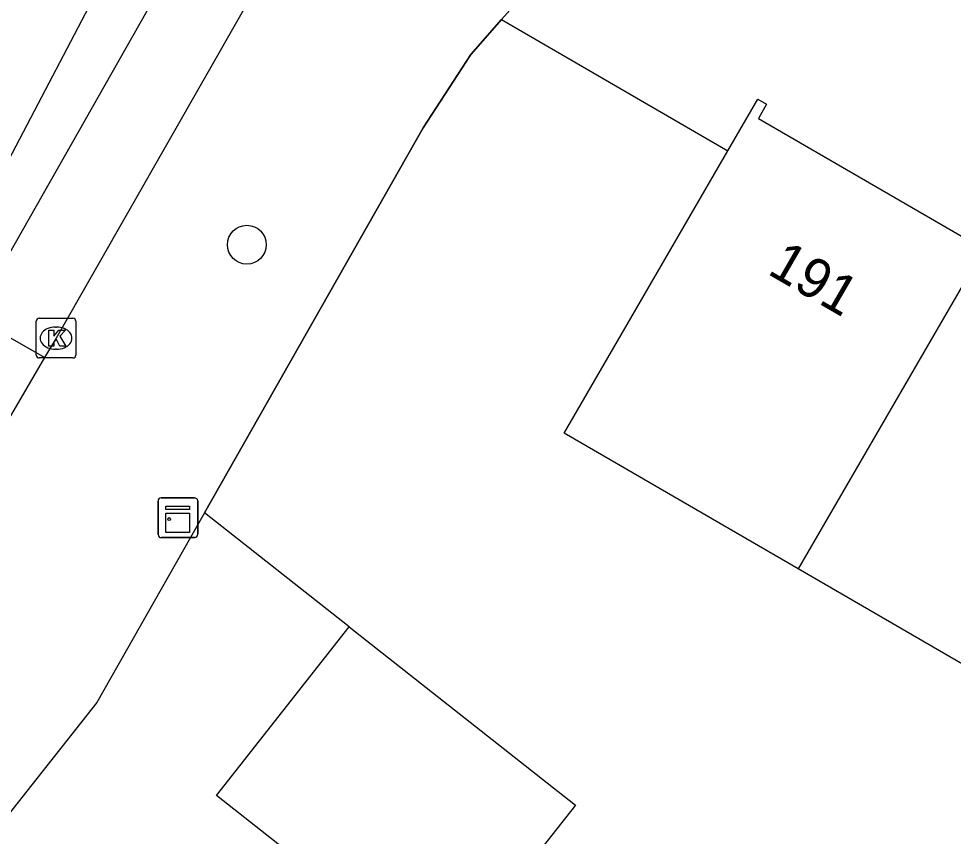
# Model space of a CAD drawing. Extents: x 160158 to 160921, y 381517 to 382041.
# Drawn here: x 160643.01 to 160666.58, y 381843.43 to 381864.05 of the extents above; entities that cross this region are included whole.
import ezdxf

# ---------------------------------------------------------------- set-up
doc = ezdxf.new("R2010")
doc.units = 0
for name, color, linetype in [('IMGEO_Boom', 7, 'Continuous'), ('IMGEO_Fietspad_open', 7, 'Continuous'), ('IMGEO_Kast', 7, 'Continuous'), ('IMGEO_Kolk', 7, 'Continuous'), ('IMGEO_Muur', 7, 'Continuous'), ('IMGEO_Pand', 7, 'Continuous'), ('IMGEO_Pand_nummerreeks', 7, 'Continuous'), ('IMGEO_Rijbaan_lokaal_gesloten', 7, 'Continuous'), ('IMGEO_Rijbaan_lokaal_open', 7, 'Continuous'), ('IMGEO_Voetpad_open', 7, 'Continuous')]:
    doc.layers.add(name, color=color, linetype=linetype)

msp = doc.modelspace()

# ---------------------------------------------------------------- linework, layer by layer
at = {"layer": 'IMGEO_Boom'}
msp.add_circle((160648.766, 381858.348), 0.489, dxfattribs=at)
at = {"layer": 'IMGEO_Fietspad_open'}
for points in [[(160653.156, 381872.105), (160648.639, 381864.194), (160643.955, 381855.993), (160643.662, 381855.505)], [(160641.866, 381856.528), (160648.195, 381867.674)]]:
    msp.add_lwpolyline(points, dxfattribs=at)
at = {"layer": 'IMGEO_Kast'}
for p, q in [((160646.528, 381851.04), (160646.528, 381851.881)), ((160646.528, 381851.881), (160646.528, 381851.04)), ((160646.603, 381851.965), (160647.444, 381851.965)), ((160647.444, 381851.965), (160646.603, 381851.965)), ((160647.528, 381851.89), (160647.528, 381851.049)), ((160647.528, 381851.049), (160647.528, 381851.89)), ((160647.453, 381850.965), (160646.612, 381850.965)), ((160646.612, 381850.965), (160647.453, 381850.965))]:
    msp.add_line(p, q, dxfattribs=at)
for points in [[(160646.723, 381851.755), (160647.323, 381851.755), (160647.323, 381851.67), (160646.723, 381851.67), (160646.723, 381851.755)], [(160646.723, 381851.58), (160647.323, 381851.58), (160647.323, 381851.091), (160646.723, 381851.091), (160646.723, 381851.58)]]:
    msp.add_lwpolyline(points, dxfattribs=at)
msp.add_circle((160646.807, 381851.429), 0.0377, dxfattribs=at)
for centre, start, end in [((160646.606, 381851.887), 92.4484, 184.2845), ((160646.606, 381851.887), 92.4484, 184.2845), ((160647.45, 381851.887), 2.4484, 94.2845), ((160647.45, 381851.887), 2.4484, 94.2845), ((160646.606, 381851.043), 182.4484, 274.2845), ((160646.606, 381851.043), 182.4484, 274.2845), ((160647.45, 381851.043), 272.4484, 4.2845), ((160647.45, 381851.043), 272.4484, 4.2845)]:
    msp.add_arc(centre, 0.0779, start, end, dxfattribs=at)
at = {"layer": 'IMGEO_Kolk'}
for p, q in [((160643.454, 381855.567), (160643.454, 381856.419)), ((160643.529, 381856.493), (160644.381, 381856.493)), ((160644.455, 381856.419), (160644.455, 381855.567)), ((160643.942, 381856.273), (160643.967, 381856.273)), ((160643.965, 381855.713), (160643.94, 381855.713)), ((160644.381, 381855.493), (160643.529, 381855.493))]:
    msp.add_line(p, q, dxfattribs=at)
for points in [[(160643.454, 381855.567), (160643.454, 381856.419)], [(160643.529, 381856.493), (160644.381, 381856.493)], [(160644.455, 381856.419), (160644.455, 381855.567)], [(160643.775, 381856.193), (160643.898, 381856.193), (160643.898, 381856.042), (160644.028, 381856.193), (160644.192, 381856.193), (160644.046, 381856.042), (160644.199, 381855.793), (160644.047, 381855.793), (160643.962, 381855.957), (160643.898, 381855.89), (160643.898, 381855.793), (160643.775, 381855.793), (160643.775, 381856.193)], [(160644.381, 381855.493), (160643.529, 381855.493)]]:
    msp.add_lwpolyline(points, dxfattribs=at)
for centre, start, end in [((160643.531, 381856.417), 91.552, 178.448), ((160643.531, 381856.417), 91.552, 178.448), ((160644.379, 381856.417), 1.552, 88.448), ((160644.379, 381856.417), 1.552, 88.448), ((160643.531, 381855.569), 181.552, 268.448), ((160643.531, 381855.569), 181.552, 268.448), ((160644.379, 381855.569), 271.552, 358.448), ((160644.379, 381855.569), 271.552, 358.448)]:
    msp.add_arc(centre, 0.0765, start, end, dxfattribs=at)
for centre, major_axis, ratio, start_param, end_param in [((160643.941, 381855.993), (-0.387, 0.002), 0.722429, 4.712389, 7.853982), ((160643.966, 381855.993), (-0.39, 0.002), 0.717154, 1.570796, 4.712389)]:
    msp.add_ellipse(centre, major_axis=major_axis, ratio=ratio, start_param=start_param, end_param=end_param, dxfattribs=at)
at = {"layer": 'IMGEO_Muur'}
for points in [[(160647.699, 381851.584), (160653.212, 381861.298), (160654.415, 381863.144), (160655.188, 381864.027)], [(160655.188, 381864.027), (160660.898, 381860.716)], [(160651.347, 381848.713), (160647.699, 381851.584)]]:
    msp.add_lwpolyline(points, dxfattribs=at)
at = {"layer": 'IMGEO_Pand'}
for points in [[(160662.665, 381850.178), (160656.769, 381853.597), (160660.898, 381860.716), (160661.65, 381862.014), (160661.869, 381861.887), (160661.664, 381861.534), (160667.164, 381858.345), (160667.363, 381858.688), (160667.544, 381858.583)], [(160667.544, 381858.583), (160662.665, 381850.178)], [(160668.437, 381846.831), (160662.665, 381850.178)], [(160654.742, 381839.152), (160647.999, 381844.459), (160651.347, 381848.713), (160657.053, 381844.222), (160655.733, 381842.545), (160656.729, 381841.761)]]:
    msp.add_lwpolyline(points, dxfattribs=at)
at = {"layer": 'IMGEO_Rijbaan_lokaal_gesloten'}
for points in [[(160643.662, 381855.505), (160641.866, 381856.528)], [(160643.662, 381855.505), (160642.317, 381853.209), (160638.774, 381847.331), (160638.255, 381846.511)]]:
    msp.add_lwpolyline(points, dxfattribs=at)
at = {"layer": 'IMGEO_Rijbaan_lokaal_open'}
msp.add_lwpolyline([(160640.968, 381857.017), (160641.01, 381857.152), (160646.912, 381868.406)], dxfattribs=at)
at = {"layer": 'IMGEO_Voetpad_open'}
msp.add_lwpolyline([(160664.857, 381866.115), (160662.715, 381866.57), (160660.296, 381866.624), (160658.571, 381866.17), (160657.082, 381865.462), (160655.682, 381864.592), (160655.188, 381864.027), (160654.415, 381863.144), (160653.212, 381861.298), (160647.699, 381851.584), (160644.987, 381846.807), (160615.493, 381809.458), (160615.388, 381809.332)], dxfattribs=at)

# ---------------------------------------------------------------- texts
at = {"layer": 'IMGEO_Pand_nummerreeks'}
msp.add_text('191', height=1, rotation=329.9307, dxfattribs=at).set_placement((160661.863, 381857.628))

doc.saveas('drawing.dxf')
